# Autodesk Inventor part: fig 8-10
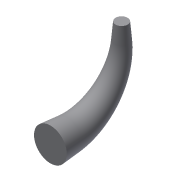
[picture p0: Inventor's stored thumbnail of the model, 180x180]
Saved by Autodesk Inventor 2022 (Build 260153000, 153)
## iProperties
Created: 2001-12
Part Number: fig 8-10
Document SubType Name: Modeling
Designer: CADSoft
Density: 1 g/cm^3
Material: Generic
Appearance: Default
Control State: 0
Master: False
Checked Out: False
Shininess: 77.0
Length Units: 11269
Angle Units: 11279
Time Units: 11290
Mass Units: 11283
Length Display Precision: 3
Angle Display Precision: 2
Density: 0.0
Volumn: 0.0
Area: 0.0
PropertySet Name: Model Information
Author: CADSoft
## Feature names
1. Sweep7
## Parameters: d4 = 15 mm, d5 = 15 mm, d13 = -5 deg, d14 = 0
